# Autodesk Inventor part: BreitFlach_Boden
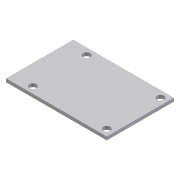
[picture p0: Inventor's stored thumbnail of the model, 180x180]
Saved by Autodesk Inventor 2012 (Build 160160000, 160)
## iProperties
Company: CAD-Verlag
Created: 2004-09
Part Number: BreitFlach_Boden
Document SubType Name: Modeling
Designer: Greiling
Manufacturer: Standard
Standards Organization: Custom
Density: 1 g/cm^3
Checked By: Jürgen Kronas
Stock Number: 10-10003
Material: Standard
Author: Juergen Kronas
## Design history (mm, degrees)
sketch "Skizze1"
  geometry: L1 (0, 140)-(0, -140) reference; L2 (-210, 0)-(210, 0) reference; L3 (-210, 0)-(210, 0) reference; L4 (0, -140)-(0, 140) reference; L5 (-150, 100)-(150, 100); L6 (150, 100)-(150, -100); L7 (150, -100)-(-150, -100); L8 (-150, -100)-(-150, 100); 1 further point
  constraints: 8 end point, 2 parallel, 1 horizontal, 1 perpendicular, 2 other
  dimensions: "d0" = 200 distance of L7.end L5.start; "d1" = 300 distance of L5.start L5.end
extrude "Extrusion1" new body sketch "Skizze1" distance "d2" = 10; taper "d3" = 0 deg
sketch "Skizze2"
  geometry: L1 (150, 100)-(150, -100) reference; L2 (150, -100)-(-150, -100) reference; L3 (0, 140)-(0, -140) reference; L4 (-210, 0)-(210, 0) reference; L5 (-210, 0)-(210, 0) reference; L6 (0, -140)-(0, 140) reference; 5 further points
  constraints: 1 horizontal, 1 vertical, 3 other
  dimensions: "d4" = 80 distance from line of L4 point (130, 80); "d5" = 20 distance from line of point (130, 80) L1; "d8" = 220 distance of point (130, 80) point (-90, 80); "d11" = 160 distance of point (130, 80) point (130, -80)
hole "Bohrung1" sketch "Skizze2" at (130, 80), (-90, 80), (130, -80), (-90, -80) diameter "d14" = 21; stored, may be unused: countersink angle "d18" = 90 deg, drill point angle "d20" = 118 deg; dims "d15" = 6, "d16" = 4, "d17" = 2, "d19" = 8
node "Volumenkörper1"
node "Volumenkörpern"
node "Oberflächenkörpern"
